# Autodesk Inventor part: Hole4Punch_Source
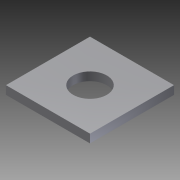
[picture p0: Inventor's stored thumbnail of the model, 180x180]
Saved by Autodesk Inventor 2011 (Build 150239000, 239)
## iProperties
Created: 2007-02
Part Number: Hole4Punch_Source
Material: Default
Document SubType Name: Sheet Metal
Designer: Autodesk, Inc.
Mass: 0.0874336 g
Surface Area: 2.27434 cm^2
Volume: 0.0874336 cm^3
Density: 1 g/cm^3
Sheet Metal Rule: 1 mm
Author: Autodesk, Inc.
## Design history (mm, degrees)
node "Face1"
  sketch "Sketch1"
    geometry: L1 (-5, 5)-(5, 5); L2 (5, 5)-(5, -5); L3 (5, -5)-(-5, -5); L4 (-5, -5)-(-5, 5); L5 (-5, 5)-(5, -5); 2 further points
    constraints: 10 end point, 2 parallel, 1 coincident, 1 horizontal, 1 midpoint, 1 perpendicular
    dimensions: "d0" = 10 distance of L2.end L3.end; "d1" = 10 distance of L1.end L2.end (= d0)
sketch "Sketch2"
  geometry: C1 r 2 at (0, 0); 2 further points
  constraints: 2 coincident, 1 centre point
  dimensions: "d3" = 4 diameter of C1
cut "Cut1" sketch "Sketch2" dims "d4" = 1 (= Thickness), "d5" = 0
body "Solid1"
face "Plate1" dims "Thickness" = 1
other parameters: "BendRadius" = 0.5, "BendReliefWidth" = 1 (= Thickness), "BendReliefDepth" = 0.5 (= 0.5 x Thickness), "CornerReliefSize" = 4 (= 4 x Thickness), "SeamGap" = 0.01, "MinimumRemnant" = 2 (= 2 x Thickness), "TransitionRadius" = 0.5 (= BendRadius), "JacobiRadiusSize" = 1 (= Thickness), "d2" = 0.5 (= BendRadius), "GapSize" = 1 (= Thickness)
